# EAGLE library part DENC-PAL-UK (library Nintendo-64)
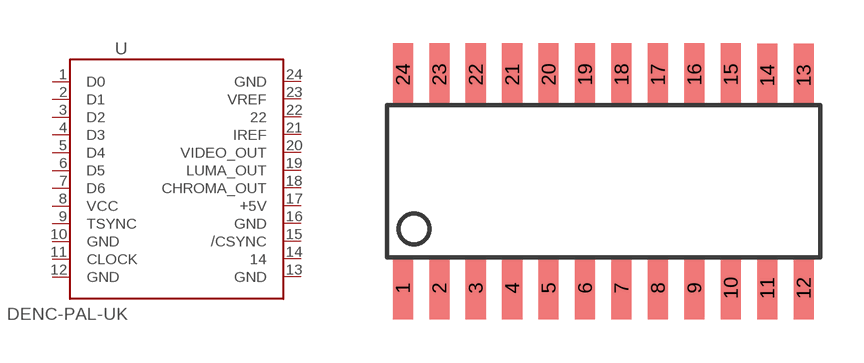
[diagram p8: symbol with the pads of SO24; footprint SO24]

Designator prefix -

## DENC-PAL-UK  [SO24]
1  D0  in
2  D1  in
3  D2  in
4  D3  in
5  D4  in
6  D5  in
7  D6  in
8  VCC  pwr
9  TSYNC  in
10  GND  pwr
11  CLOCK  in
12  GND  pwr
13  GND  pwr
14  14
15  /CSYNC  out
16  GND  pwr
17  +5V  pwr
18  CHROMA_OUT  out
19  LUMA_OUT  out
20  VIDEO_OUT  out
21  IREF  in
22  22
23  VREF  in
24  GND  pwr

## Footprint SO24 (pad centres in mm)
smd 0.7 x 2.2: 1 -7.62,-3.707; 2 -6.35,-3.707; 3 -5.08,-3.707; 4 -3.81,-3.707; 5 -2.54,-3.707; 6 -1.27,-3.707; 7 0,-3.707; 8 1.27,-3.707; 9 2.54,-3.707; 10 3.81,-3.707; 11 5.08,-3.707; 12 6.35,-3.707; 13 6.35,3.707; 14 5.08,3.707; 15 3.81,3.739; 16 2.54,3.739; 17 1.27,3.739; 18 0,3.739; 19 -1.27,3.739; 20 -2.54,3.739; 21 -3.81,3.739; 22 -5.08,3.739; 23 -6.35,3.739; 24 -7.62,3.739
